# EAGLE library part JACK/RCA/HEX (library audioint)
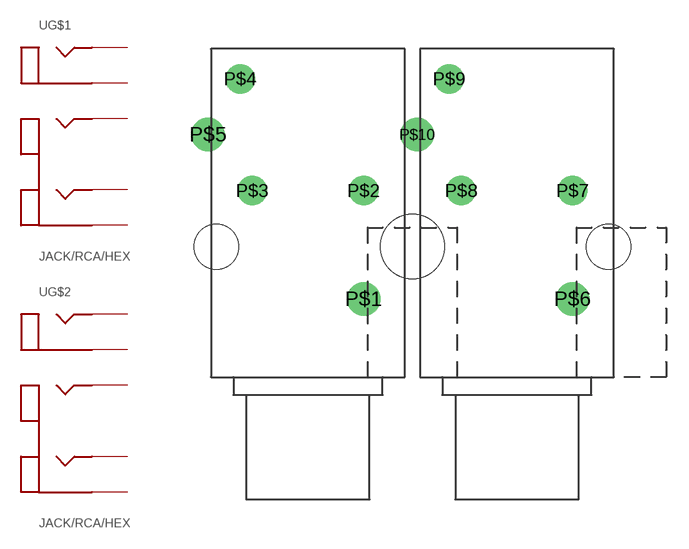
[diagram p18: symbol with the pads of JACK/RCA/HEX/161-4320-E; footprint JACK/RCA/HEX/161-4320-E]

Designator prefix -; gates G$1=JACK/RCA/TRIPLE G$2=JACK/RCA/TRIPLE

## JACK/RCA/HEX  [JACK/RCA/HEX/161-4320-E]
P$1  G$1:P$2
P$2  G$1:P$3
P$3  G$1:P$1
P$4  G$1:P$5
P$5  G$1:P$4
P$6  G$2:P$2
P$7  G$2:P$3
P$8  G$2:P$1
P$9  G$2:P$5
P$10  G$2:P$4

## Footprint JACK/RCA/HEX/161-4320-E (pad centres in mm)
drill 1.499 round: P$1 3.734,5.232; P$5 -6.706,16.256; P$6 17.755,5.232; P$10 7.315,16.256
drill 1.321 round: P$2 3.734,12.497; P$3 -3.734,12.497; P$4 -4.547,19.99; P$7 17.755,12.497; P$8 10.287,12.497; P$9 9.474,19.99
hole 2.997 at -6.147,8.738
hole 2.997 at 20.168,8.738
hole 4.318 at 7.01,8.738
